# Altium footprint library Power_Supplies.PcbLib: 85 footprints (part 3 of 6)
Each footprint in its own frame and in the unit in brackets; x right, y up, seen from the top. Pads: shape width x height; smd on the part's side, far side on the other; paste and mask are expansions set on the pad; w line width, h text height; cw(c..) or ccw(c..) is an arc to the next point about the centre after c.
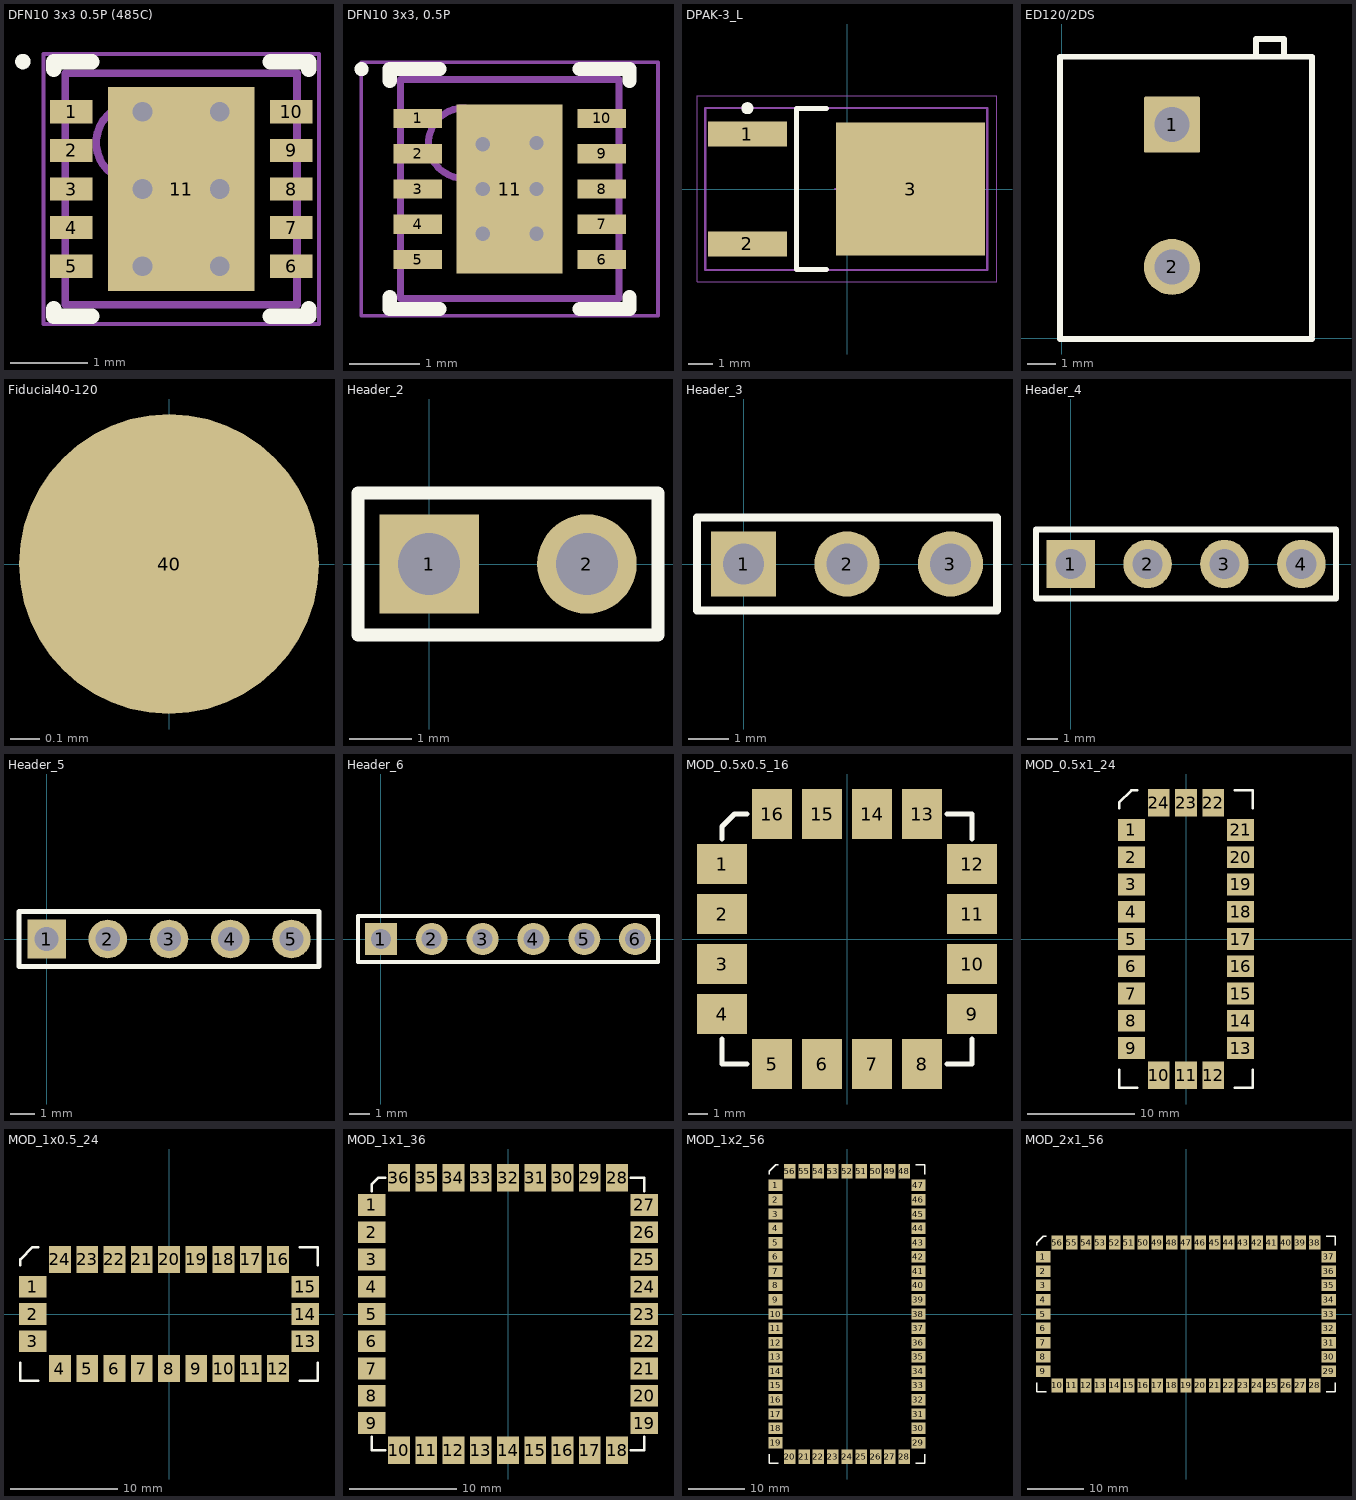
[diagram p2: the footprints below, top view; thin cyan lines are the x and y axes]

## DFN10 3x3 0.5P (485C) [mm] "DFN10 3x3 0.5P, CASE (485C, ISSUE E"
height 1
pads (11):
  rect 0.55x0.3 smd: 1(4168.3,4170.725) 2(4168.3,4170.225) 3(4168.3,4169.725) 4(4168.3,4169.225) 5(4168.3,4168.725) 6(4171.15,4168.725) 7(4171.15,4169.225) 8(4171.15,4169.725) 9(4171.15,4170.225) 10(4171.15,4170.725)
  rect 1.9x2.64 smd: 11(4169.725,4169.725)
via 4169.225,4170.725 diameter 0.508 hole 0.254
via 4170.225,4170.725 diameter 0.508 hole 0.254
via 4169.225,4169.725 diameter 0.508 hole 0.254
via 4170.225,4169.725 diameter 0.508 hole 0.254
via 4169.225,4168.725 diameter 0.508 hole 0.254
via 4170.225,4168.725 diameter 0.508 hole 0.254
Top Overlay:
  circle w0.1: c4167.675,4171.375 r0.05
  lines w0.2: 4168.075,4168.175 4168.075,4168.075 4168.57,4168.075 ; 4168.075,4171.275 4168.075,4171.375 4168.57,4171.375 ; 4170.88,4168.075 4171.375,4168.075 4171.375,4168.175 ; 4170.88,4171.375 4171.375,4171.375 4171.375,4171.275
Mechanical 13:
  circle w0.1: c4169.125,4170.325 r0.5
  lines w0.1: 4168.225,4168.225 4168.225,4171.225 4171.225,4171.225 4171.225,4168.225 4168.225,4168.225
Mechanical 15:
  lines w0.05: 4167.94,4167.975 4167.94,4171.475 4171.51,4171.475 4171.51,4167.975 4167.94,4167.975
  lines w0.1: 4169.225,4169.725 4170.225,4169.725 ; 4169.725,4169.225 4169.725,4170.225
3D body "DFN10 3x3 0.5P (485C).step": height 1, standoff 0, extent -5559532.411,-5559532.41 -5559529.409,-5559529.41

## DFN10 3x3, 0.5P [mm] "DFN10 3x3, 0.5P, CASE 507AG, Issue A"
height 0.9
pads (11):
  rect 0.69x0.27 smd: 1(-1792.088,-1789.783) 2(-1792.088,-1790.283) 3(-1792.088,-1790.783) 4(-1792.088,-1791.283) 5(-1792.088,-1791.783) 6(-1789.478,-1791.783) 7(-1789.478,-1791.283) 8(-1789.478,-1790.783) 9(-1789.478,-1790.283) 10(-1789.478,-1789.783)
  rect 1.5x2.4 smd: 11(-1790.783,-1790.783)
via -1790.402,-1791.418 diameter 0.5 hole 0.2
via -1790.402,-1790.783 diameter 0.5 hole 0.2
via -1790.402,-1790.133 diameter 0.5 hole 0.2
via -1791.164,-1791.418 diameter 0.5 hole 0.2
via -1791.164,-1790.783 diameter 0.5 hole 0.2
via -1791.164,-1790.148 diameter 0.5 hole 0.2
Top Overlay:
  circle w0.1: c-1792.883,-1789.083 r0.05
  lines w0.2: -1792.483,-1792.318 -1792.483,-1792.483 -1791.778,-1792.483 ; -1792.483,-1789.248 -1792.483,-1789.083 -1791.778,-1789.083 ; -1789.788,-1792.483 -1789.083,-1792.483 -1789.083,-1792.318 ; -1789.788,-1789.083 -1789.083,-1789.083 -1789.083,-1789.248
Mechanical 13:
  circle w0.1: c-1791.433,-1790.133 r0.5
  lines w0.1: -1792.333,-1792.333 -1792.333,-1789.233 -1789.233,-1789.233 -1789.233,-1792.333 -1792.333,-1792.333
Mechanical 15:
  lines w0.05: -1792.888,-1792.583 -1792.888,-1788.983 -1788.678,-1788.983 -1788.678,-1792.583 -1792.888,-1792.583
  lines w0.1: -1791.283,-1790.783 -1790.283,-1790.783 ; -1790.783,-1791.283 -1790.783,-1790.283
3D body "DFN10 3x3, 0.5P.step": height 0.9, standoff 0, extent -12701.551,-12701.55 -12698.449,-12698.45

## DPAK-3_L [mm] "D-PAK, 3-Pads, Body 8.31x6.73mm (max), IPC Low Density"
height 2.38
pads (3):
  rect 3.3x1.05 smd: 1(-4.15,2.29) 2(-4.15,-2.29)
  rect 6.2x5.55 smd: 3(2.65,0)
Top Overlay:
  circle w0.25: c-4.15,3.365 r0.125
  lines w0.2: -0.85,-3.35 -2.1,-3.35 -2.1,3.35 -0.85,3.35
Mechanical 13:
  lines w0.1: -5.9,-3.375 -5.9,3.375 5.842,3.375 5.842,-3.375 -5.9,-3.375
Mechanical 15:
  lines w0.05: -6.25,-3.875 -6.25,3.875 6.25,3.875 6.25,-3.875 -6.25,-3.875
  lines w0.1: -0.5,0 0.5,0 ; 0,-0.5 0,0.5
3D body "DPAK-3_2L.step": height 2.37, standoff -0.03, extent -4.955,-3.367 5.145,3.367

## ED120/2DS [mm] "Large Screw Terminal"
pads (2):
  rrect5% 2x2 hole 1.25: 1(3.937,7.62)
  round 2 hole 1.25: 2(3.937,2.54)
Top Overlay:
  lines w0.2: -0.063,9.965 -0.063,-0.035 8.937,-0.035 ; -0.063,10.04 8.937,10.04 8.937,0.065 ; 6.937,10.04 6.937,10.68 7.937,10.68 7.937,10.04
Mechanical 5:
  lines w0.1: -0.063,9.965 -0.063,-0.035 8.937,-0.035 8.937,10.04 -0.063,10.04 ; 6.937,10.04 6.937,10.68 7.937,10.68 7.937,10.04
3D body "ED1202DS.stp": height 13, standoff -4, extent -0.063,0 8.937,10.86

## Fiducial40-120 [mil]
pads (1):
  round 40 smd mask+40: 40(0,0)

## Header_2 [mm]
pads (2):
  rect 1.6x1.6 hole 1: 1(0,0)
  round 1.6 hole 1: 2(2.54,0)
Top Overlay:
  lines w0.203: -1.143,-1.143 3.683,-1.143 3.683,1.143 -1.143,1.143 -1.143,-1.143
3D body "Header_Male_2Pin_2.54mm.STEP": height 8.54, standoff -3, extent -1.27,-1.245 3.81,1.245

## Header_3 [mm]
pads (3):
  rect 1.6x1.6 hole 1: 1(0,0)
  round 1.6 hole 1: 2(2.54,0) 3(5.08,0)
Top Overlay:
  lines w0.203: -1.143,-1.143 -1.143,1.143 6.223,1.143 6.223,-1.143 -1.143,-1.143
3D body "Header_Male_3Pin_2,54mm.STEP": height 8.54, standoff -3, extent -1.27,-1.245 6.35,1.245

## Header_4 [mm]
pads (4):
  rect 1.6x1.6 hole 1: 1(0,0)
  round 1.6 hole 1: 2(2.54,0) 3(5.08,0) 4(7.62,0)
Top Overlay:
  lines w0.203: -1.143,-1.143 8.763,-1.143 8.763,1.143 -1.143,1.143 -1.143,-1.143
3D body "Header_Male_2Pin_2.54mm.STEP": height 8.54, standoff -3, extent -1.27,-1.245 3.81,1.245
3D body "Header_Male_2Pin_2.54mm.STEP": height 8.54, standoff -3, extent 3.81,-1.245 8.89,1.245

## Header_5 [mm]
pads (5):
  rect 1.6x1.6 hole 1: 1(0,0)
  round 1.6 hole 1: 2(2.54,0) 3(5.08,0) 4(7.62,0) 5(10.16,0)
Top Overlay:
  lines w0.203: -1.143,-1.143 -1.143,1.143 11.303,1.143 11.303,-1.143 -1.143,-1.143
3D body "Header_Male_2Pin_2.54mm.STEP": height 8.54, standoff -3, extent -1.27,-1.245 3.81,1.245
3D body "Header_Male_3Pin_2,54mm.STEP": height 8.54, standoff -3, extent 3.81,-1.245 11.43,1.245

## Header_6 [mm]
pads (6):
  rect 1.6x1.6 hole 1: 1(0,0)
  round 1.6 hole 1: 2(2.54,0) 3(5.08,0) 4(7.62,0) 5(10.16,0) 6(12.7,0)
Top Overlay:
  lines w0.203: -1.143,-1.143 13.843,-1.143 13.843,1.143 -1.143,1.143 -1.143,-1.143
3D body "Header_Male_2Pin_2.54mm.STEP": height 8.54, standoff -3, extent -1.27,-1.245 3.81,1.245
3D body "Header_Male_2Pin_2.54mm.STEP": height 8.54, standoff -3, extent 3.81,-1.245 8.89,1.245
3D body "Header_Male_2Pin_2.54mm.STEP": height 8.54, standoff -3, extent 8.89,-1.245 13.97,1.245

## MOD_0.5x0.5_16 [mil]
pads (16):
  rect 100x80 smd: 1(-250,150) 2(-250,50) 3(-250,-50) 4(-250,-150) 9(250,-150) 10(250,-50) 11(250,50) 12(250,150)
  rect 80x100 smd: 5(-150,-250) 6(-50,-250) 7(50,-250) 8(150,-250) 13(150,250) 14(50,250) 15(-50,250) 16(-150,250)
Top Overlay:
  lines w10: -250,-200 -250,-250 -200,-250 ; -250,200 -250,225 -225,250 -200,250 ; 200,-250 250,-250 250,-200 ; 200,250 250,250 250,200

## MOD_0.5x1_24 [mil]
pads (24):
  rect 100x80 smd: 1(-200,400) 2(-200,300) 3(-200,200) 4(-200,100) 5(-200,0) 6(-200,-100) 7(-200,-200) 8(-200,-300) 9(-200,-400) 13(200,-400) 14(200,-300) 15(200,-200) 16(200,-100) 17(200,0) 18(200,100) 19(200,200) 20(200,300) 21(200,400)
  rect 80x100 smd: 10(-100,-500) 11(0,-500) 12(100,-500) 22(100,500) 23(0,500) 24(-100,500)
Top Overlay:
  lines w10: -245,-480 -245,-545 -180,-545 ; -245,480 -245,500 -200,545 -180,545 ; 180,-545 245,-545 245,-480 ; 180,545 245,545 245,480

## MOD_1x0.5_24 [mil]
pads (24):
  rect 100x80 smd: 1(-500,100) 2(-500,0) 3(-500,-100) 13(500,-100) 14(500,0) 15(500,100)
  rect 80x100 smd: 4(-400,-200) 5(-300,-200) 6(-200,-200) 7(-100,-200) 8(0,-200) 9(100,-200) 10(200,-200) 11(300,-200) 12(400,-200) 16(400,200) 17(300,200) 18(200,200) 19(100,200) 20(0,200) 21(-100,200) 22(-200,200) 23(-300,200) 24(-400,200)
Top Overlay:
  lines w10: -545,-180 -545,-245 -480,-245 ; -545,180 -545,200 -500,245 -480,245 ; 480,-245 545,-245 545,-180 ; 480,245 545,245 545,180

## MOD_1x1_36 [mil]
pads (36):
  rect 100x80 smd: 1(-500,400) 2(-500,300) 3(-500,200) 4(-500,100) 5(-500,0) 6(-500,-100) 7(-500,-200) 8(-500,-300) 9(-500,-400) 19(500,-400) 20(500,-300) 21(500,-200) 22(500,-100) 23(500,0) 24(500,100) 25(500,200) 26(500,300) 27(500,400)
  rect 80x100 smd: 10(-400,-500) 11(-300,-500) 12(-200,-500) 13(-100,-500) 14(0,-500) 15(100,-500) 16(200,-500) 17(300,-500) 18(400,-500) 28(400,500) 29(300,500) 30(200,500) 31(100,500) 32(0,500) 33(-100,500) 34(-200,500) 35(-300,500) 36(-400,500)
Top Overlay:
  lines w10: -500,-450 -500,-500 -450,-500 ; -500,450 -500,475 -475,500 -450,500 ; 450,-500 500,-500 500,-450 ; 450,500 500,500 500,450

## MOD_1x2_56 [mil]
pads (56):
  rect 100x80 smd: 1(-500,900) 2(-500,800) 3(-500,700) 4(-500,600) 5(-500,500) 6(-500,400) 7(-500,300) 8(-500,200) 9(-500,100) 10(-500,0) 11(-500,-100) 12(-500,-200) 13(-500,-300) 14(-500,-400) 15(-500,-500) 16(-500,-600) 17(-500,-700) 18(-500,-800) 19(-500,-900) 29(500,-900) 30(500,-800) 31(500,-700) 32(500,-600) 33(500,-500) 34(500,-400) 35(500,-300) 36(500,-200) 37(500,-100) 38(500,0) 39(500,100) 40(500,200) 41(500,300) 42(500,400) 43(500,500) 44(500,600) 45(500,700) 46(500,800) 47(500,900)
  rect 80x100 smd: 20(-400,-1000) 21(-300,-1000) 22(-200,-1000) 23(-100,-1000) 24(0,-1000) 25(100,-1000) 26(200,-1000) 27(300,-1000) 28(400,-1000) 48(400,1000) 49(300,1000) 50(200,1000) 51(100,1000) 52(0,1000) 53(-100,1000) 54(-200,1000) 55(-300,1000) 56(-400,1000)
Top Overlay:
  lines w10: -545,-980 -545,-1045 -480,-1045 ; -545,980 -545,1000 -500,1045 -480,1045 ; 480,-1045 545,-1045 545,-980 ; 480,1045 545,1045 545,980

## MOD_2x1_56 [mil]
pads (56):
  rect 100x80 smd: 1(-1000,400) 2(-1000,300) 3(-1000,200) 4(-1000,100) 5(-1000,0) 6(-1000,-100) 7(-1000,-200) 8(-1000,-300) 9(-1000,-400) 29(1000,-400) 30(1000,-300) 31(1000,-200) 32(1000,-100) 33(1000,0) 34(1000,100) 35(1000,200) 36(1000,300) 37(1000,400)
  rect 80x100 smd: 10(-900,-500) 11(-800,-500) 12(-700,-500) 13(-600,-500) 14(-500,-500) 15(-400,-500) 16(-300,-500) 17(-200,-500) 18(-100,-500) 19(0,-500) 20(100,-500) 21(200,-500) 22(300,-500) 23(400,-500) 24(500,-500) 25(600,-500) 26(700,-500) 27(800,-500) 28(900,-500) 38(900,500) 39(800,500) 40(700,500) 41(600,500) 42(500,500) 43(400,500) 44(300,500) 45(200,500) 46(100,500) 47(0,500) 48(-100,500) 49(-200,500) 50(-300,500) 51(-400,500) 52(-500,500) 53(-600,500) 54(-700,500) 55(-800,500) 56(-900,500)
Top Overlay:
  lines w10: -1045,-480 -1045,-545 -980,-545 ; -1045,480 -1045,500 -1000,545 -980,545 ; 980,-545 1045,-545 1045,-480 ; 980,545 1045,545 1045,480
